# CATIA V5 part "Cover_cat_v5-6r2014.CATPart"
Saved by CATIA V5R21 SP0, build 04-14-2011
Part number: Cover
Bounding box of the stored display mesh (mm): x -126.806 to 88.9, y -112.451 to 112.451, z 0 to 76.2
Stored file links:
  D:\CATIA V5R21 E-RESOURCES\CATIA-V5R21\catia-v5r21-Tut\c12-catia-v5r21-tut\c12-catia-v5r21-tut01\Cover_cat_v5r21.CATPart
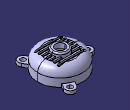
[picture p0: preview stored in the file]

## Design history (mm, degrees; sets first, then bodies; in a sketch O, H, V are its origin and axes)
Body1 (main body)
  Sketch1 on xy-plane, origin (0, 0, 0), H (1, 0, 0), V (0, 1, 0)
    circle A1 centre (0, 0) radius 88.9
    radius A1 = 88.9
  Pad1: profile Sketch1, direction (0, 0, 1), length 63.5
  Fillet1: radius 31.75, on 1 edge
  Shell1: ExtOffset 0, Face face, IntOffset 6.35
  Sketch2 on face of Pad1, origin (0, 0, 63.5), H (1, 0, 0), V (0, 1, 0)
    construction line L1 (-50.8, 0) -> (50.8, 0)
    point P1 (-50.8, 0)
    line L2 (-50.8, 4.445) -> (50.8, 4.445)
    line L3 (50.8, -4.445) -> (-50.8, -4.445)
    arc A1 centre (50.8, 0) radius 4.445 from (50.8, 4.445) to (50.8, -4.445) cw
    arc A2 centre (-50.8, 0) radius 4.445 from (-50.8, -4.445) to (-50.8, 4.445) cw
    length L1 = 101.6
    radius A1 = 4.445
    distance P1 V = 50.8
    coincidence: P1 H
    horizontal: L1 H
    tangency: A1 L2, A2 L2, A1 L3, A2 L3
    parallelism: L1 L2
  Pocket1: profile Sketch2, direction (0, 0, -1), length 12.7
  RectPattern1: of Pocket1, direction 1 instances 1, spacing 15.24, along xy-plane, direction 2 instances 7, spacing 15.24, along xy-plane, Nv 4
  Sketch3 on face of Shell1, origin (0, 0, 57.15), H (1, 0, 0), V (0, -1, 0)
    circle A1 centre (0, 0) radius 31.75
    radius A1 = 31.75
  Pad2: profile Sketch3, direction (0, 0, 1), length 19.05
  Fillet2: radius 5.08, on 1 edge
  Sketch4 on face of Pad2, origin (0, 0, 76.2), H (1, 0, 0), V (0, 1, 0)
    circle A1 centre (0, 0) radius 19.05
    radius A1 = 19.05
  Pocket2: profile Sketch4, direction (0, 0, -1), through (limit type 6)
  Sketch5 on xy-plane, origin (0, 0, 0), H (1, 0, 0), V (0, 1, 0)
    projected arc E1 centre (0, 0) radius 88.9 from (-86.8349, 19.05) to (-86.8349, -19.05) ccw from edge of RectPattern1
    line L1 (-86.8349, 19.05) -> (-107.95, 19.05)
    line L2 (-86.8349, -19.05) -> (-107.95, -19.05)
    arc A1 centre (-107.95, 0) radius 19.05 from (-107.95, -19.05) to (-107.95, 19.05) cw
    point P5 (-107.95, 0)
    point P6 (-127, 0)
    circle A2 centre (-107.95, 0) radius 9.525
    radius A1 = 19.05
    distance V P5 = 107.95
    radius A2 = 9.525
    horizontal: L1 H, L2 H
    coincidence: A1 P6, P6 H, P5 H
    tangency: A1 L2, L1 A1
  Pad3: profile Sketch5, direction (0, 0, 1), length 12.7
  CircPattern1: of Pad3, instances 3, angular step 120, axis from xy-plane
